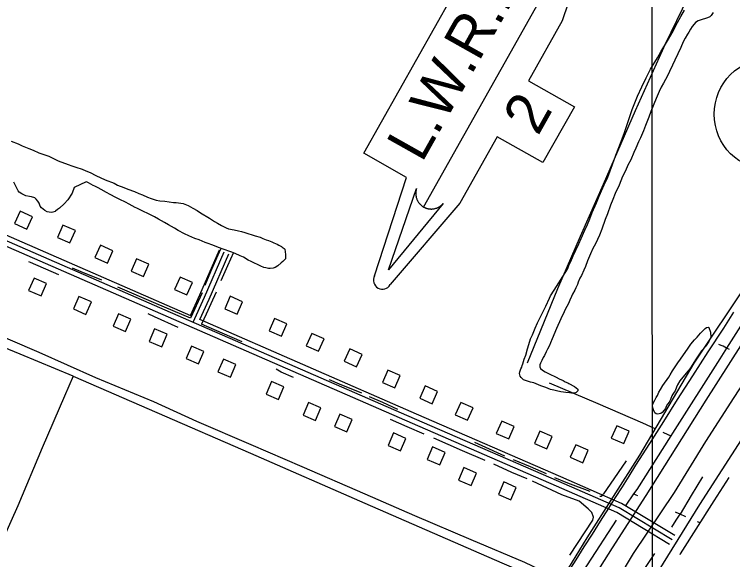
# Model space of a CAD drawing. Extents: x 3297735 to 3335592, y 670436 to 695807.
# Drawn here: x 3310478 to 3312597, y 691708 to 693317 of the extents above; entities that cross this region are included whole.
import ezdxf

# ---------------------------------------------------------------- set-up
doc = ezdxf.new("R2010")
doc.units = 0
for name, color, linetype in [('V-BLDG-OTLN', 7, 'Continuous'), ('V-DTCH-CNTR', 7, 'Continuous'), ('V-GRID-MAJR', 7, 'Continuous'), ('V-RAIL-TRAK', 7, 'Continuous'), ('V-ROAD-CNTR', 7, 'Continuous'), ('V-ROAD-IDEN', 7, 'Continuous'), ('V-SITE-VEGE', 7, 'Continuous'), ('V-TOPO-SHOR', 7, 'Continuous'), ('V-TOPO-WATR-IDEN', 7, 'Continuous')]:
    doc.layers.add(name, color=color, linetype=linetype)

msp = doc.modelspace()

# ---------------------------------------------------------------- linework, layer by layer
at = {"layer": 'V-BLDG-OTLN'}
for points in [[(3310478.7, 692699.8), (3310515.2, 692683.6), (3310531.4, 692720.2), (3310494.9, 692736.4)], [(3310605.3, 692658.8), (3310641.9, 692642.6), (3310658.1, 692679.2), (3310621.5, 692695.4)], [(3310716, 692599.5), (3310752.6, 692583.3), (3310768.8, 692619.9), (3310732.2, 692636.1)], [(3310822.4, 692559.7), (3310859, 692543.5), (3310875.2, 692580.1), (3310838.6, 692596.3)], [(3310950.8, 692505.7), (3310987.4, 692489.5), (3311003.6, 692526), (3310967, 692542.2)], [(3310572.9, 692522.9), (3310536.2, 692538.8), (3310520.3, 692502.1), (3310557.1, 692486.2)], [(3310705.3, 692468.6), (3310668.6, 692484.5), (3310652.8, 692447.8), (3310689.5, 692431.9)], [(3311098.7, 692448.6), (3311135.4, 692432.7), (3311151.3, 692469.4), (3311114.6, 692485.3)], [(3310821.9, 692418), (3310785.2, 692433.8), (3310769.4, 692397.1), (3310806.1, 692381.2)], [(3311229.5, 692383.7), (3311266, 692367.5), (3311282.2, 692404), (3311245.7, 692420.2)], [(3310928.8, 692373.1), (3310892.1, 692389), (3310876.2, 692352.3), (3310912.9, 692336.4)], [(3311339.3, 692339.2), (3311375.9, 692323), (3311392.1, 692359.6), (3311355.5, 692375.8)], [(3311037.5, 692322.4), (3311000.8, 692338.2), (3310984.9, 692301.5), (3311021.6, 692285.6)], [(3311451.5, 692293.5), (3311488, 692277.3), (3311504.2, 692313.8), (3311467.7, 692330)], [(3311131.5, 692283.6), (3311094.8, 692299.4), (3311078.9, 692262.7), (3311115.6, 692246.8)], [(3311563.8, 692231), (3311600.3, 692214.8), (3311616.5, 692251.4), (3311580, 692267.6)], [(3311273.4, 692217.6), (3311236.6, 692233.5), (3311220.8, 692196.8), (3311257.5, 692180.9)], [(3311674.2, 692184.2), (3311710.7, 692168), (3311726.9, 692204.6), (3311690.4, 692220.8)], [(3311382.3, 692155.8), (3311345.6, 692171.6), (3311329.8, 692134.9), (3311366.5, 692119.1)], [(3311778.7, 692135.3), (3311815.3, 692119.2), (3311831.5, 692155.7), (3311794.9, 692171.9)], [(3311474.9, 692121.7), (3311438.2, 692137.6), (3311422.3, 692100.9), (3311459.1, 692085)], [(3311899.9, 692080.7), (3311936.5, 692064.5), (3311952.7, 692101), (3311916.1, 692117.2)], [(3312239.2, 692066.6), (3312275.8, 692050.4), (3312292, 692087), (3312255.4, 692103.2)], [(3311633.4, 692065.9), (3311596.6, 692081.8), (3311580.8, 692045), (3311617.5, 692029.2)], [(3312012.6, 692050.9), (3312049.1, 692034.7), (3312065.3, 692071.3), (3312028.8, 692087.5)], [(3311748.9, 692024.7), (3311712.2, 692040.5), (3311696.4, 692003.8), (3311733.1, 691987.9)], [(3312118.2, 692010.4), (3312154.8, 691994.2), (3312171, 692030.8), (3312134.4, 692047)], [(3311841.4, 691963.7), (3311804.7, 691979.5), (3311788.9, 691942.8), (3311825.6, 691927)], [(3311958.6, 691921.3), (3311921.9, 691937.2), (3311906, 691900.4), (3311942.7, 691884.6)]]:
    msp.add_lwpolyline(points, close=True, dxfattribs=at)
at = {"layer": 'V-DTCH-CNTR'}
for points in [[(3312747.8, 694010.5), (3312706.8, 693904.1), (3312691, 693859.3), (3312664.3, 693798.2), (3312650.6, 693773.8), (3312638.3, 693754.1), (3312626, 693733.8), (3312613, 693711.4), (3312602.8, 693690.4), (3312573.9, 693631.7), (3312545.1, 693554.3), (3312481.3, 693402.3), (3312398.5, 693229.3), (3312309.4, 693032.6), (3312215.6, 692815.5), (3312147.7, 692661.4), (3312080.6, 692507.4), (3311991.5, 692287.5)], [(3310651.5, 692249.7), (3310495.5, 692314.6), (3310272.2, 692406.2), (3310049.6, 692502.6), (3309907.3, 692567.5), (3309884.3, 692579.9)], [(3310651.5, 692249.7), (3310626.4, 692190.3), (3310560.3, 692037.9), (3310488.6, 691866.6), (3310417.4, 691710.2), (3310375.3, 691610.6), (3310321.6, 691477.1), (3310262, 691344.5), (3310197.8, 691183.9), (3310147.1, 691059.4), (3310127.2, 691013), (3310087.6, 690919.2), (3310081, 690904.6)], [(3310651.5, 692249.7), (3310898.5, 692142.2), (3311175.3, 692022.3), (3311511.8, 691874.3), (3311893.8, 691708.5), (3311996.2, 691664.6)]]:
    msp.add_lwpolyline(points, dxfattribs=at)
at = {"layer": 'V-GRID-MAJR'}
msp.add_lwpolyline([(3312375.1, 675822.7), (3312373.9, 677215.6), (3312371.7, 679737.2), (3312369.1, 682705.7), (3312367.8, 684205.7), (3312365.9, 686440.1), (3312363.4, 689216.6), (3312360.3, 692823.2), (3312359.3, 694007.2)], dxfattribs=at)
at = {"layer": 'V-RAIL-TRAK'}
for points in [[(3312231.6, 691860.4), (3312252, 691891.7), (3312272.2, 691923.1), (3312292.2, 691954.7), (3312311.9, 691986.4), (3312353.1, 692051.1), (3312394.1, 692115.8), (3312434.8, 692180.7), (3312479.9, 692250.9), (3312525.2, 692321), (3312570.8, 692390.9), (3312600.3, 692438.3)], [(3312099, 691650.2), (3312110.7, 691669.3), (3312135.2, 691707.3), (3312159.6, 691745.4), (3312183.8, 691783.6), (3312207.8, 691821.9), (3312231.6, 691860.4)]]:
    msp.add_lwpolyline(points, dxfattribs=at)
at = {"layer": 'V-ROAD-CNTR'}
for points in [[(3313189.2, 693231.9), (3312861.3, 692717), (3312518.5, 692178.8), (3312341.6, 691897.3), (3312242.3, 691742.4), (3312038.3, 691420.5), (3311841.3, 691109), (3311668.6, 690842.8), (3311504, 690585), (3311408.2, 690444.7), (3311309.2, 690278.1), (3311173.2, 690061.5), (3311058.2, 689890.8)], [(3312419.1, 691766.1), (3312262.7, 691860.6), (3312084, 691938.6), (3311658.6, 692123.8), (3310993.2, 692414.2), (3310034.6, 692832.2), (3309899.5, 692893.8), (3309553.3, 693034.1)], [(3313225.9, 693012.8), (3312927.4, 692557.2), (3312688.4, 692164.2), (3312499.1, 691871), (3312353.9, 691636.1), (3312293.2, 691547), (3312159.4, 691339.8), (3312033.4, 691146.4), (3311880.5, 690903.5), (3311700.1, 690619.8), (3311629.8, 690502.5), (3311539.4, 690360.1), (3311438.5, 690202.4), (3311312.8, 690002.2), (3311226.4, 689864.9)], [(3312211.2, 691569.6), (3312305.1, 691726.5), (3312425.4, 691906), (3312517.7, 692057), (3312601.5, 692186.5), (3312684.8, 692313), (3312748.6, 692415.4), (3312814.9, 692521.5), (3312889.9, 692643.2), (3312978.4, 692789.2), (3313074.3, 692931.7), (3313120.6, 693003.5)], [(3310999.2, 692428), (3310999.2, 692428), (3310040.7, 692845.9), (3310005.9, 692861.8)], [(3310989.4, 689923.2), (3311166.1, 690197.8), (3311352.6, 690492.2), (3311553.7, 690809.1), (3311739.6, 691100.5), (3311901.8, 691353), (3312049.3, 691577.8), (3312168.1, 691772.4), (3312323.3, 692016.1), (3312483.8, 692287.8), (3312642.5, 692524.8), (3312756.2, 692696.5), (3312827.1, 692802.6), (3312864.6, 692857.4)], [(3312411.4, 691753.2), (3312255.8, 691847.3), (3312078, 691924.8), (3311652.6, 692110.1), (3310987.2, 692400.5), (3310028.5, 692818.5), (3309995.6, 692833.5)], [(3310998.2, 692428.4), (3311025.8, 692489.1), (3311083.3, 692622.2)], [(3311005.7, 692408.8), (3311039.5, 692483), (3311097.1, 692616.2)], [(3311025.7, 692416.4), (3311053.2, 692476.9), (3311110.9, 692610.3)], [(3312426.9, 691778.9), (3312269.6, 691874), (3312089.9, 691952.3), (3311664.6, 692137.6), (3311025.7, 692416.4)]]:
    msp.add_lwpolyline(points, dxfattribs=at)
at = {"layer": 'V-ROAD-IDEN'}
msp.add_circle((3312707.9, 693022.9), 165, dxfattribs=at)
at = {"layer": 'V-SITE-VEGE'}
for points in [[(3312070.7, 692503.6), (3312110, 692565.2), (3312110.9, 692567.2), (3312114.9, 692579.1), (3312119.4, 692588), (3312126.9, 692604.7), (3312143.8, 692639.8), (3312150.8, 692655.6), (3312161.3, 692680.3), (3312168.8, 692697), (3312176.2, 692714.3), (3312183.2, 692732.6), (3312195.2, 692760.7), (3312203.7, 692781), (3312218.1, 692814), (3312228.6, 692837.2), (3312243.1, 692874.3), (3312253, 692901.4), (3312268.5, 692941.9), (3312278, 692969.1), (3312291.5, 693010.5), (3312301, 693036.2), (3312316.4, 693076.2), (3312329.4, 693103.3), (3312341.8, 693130), (3312354.8, 693155.7), (3312375.7, 693189.2), (3312385.6, 693206.5), (3312408, 693244.5), (3312421.4, 693268.1), (3312429.4, 693284.9), (3312444.8, 693311.1), (3312455.3, 693329.3)], [(3312539.8, 693322.6), (3312534.3, 693313.7), (3312529.9, 693310.3), (3312522.9, 693306.8), (3312517, 693304.9), (3312507.6, 693302.4), (3312501.2, 693300.5), (3312495.7, 693298.5), (3312487.3, 693293.6), (3312483.3, 693288.7), (3312478.3, 693281.8), (3312473.4, 693273.9), (3312467.9, 693264.5), (3312463.9, 693258.6), (3312457, 693246.8), (3312451.5, 693235.9), (3312444.5, 693219.1), (3312427.1, 693182.1), (3312419.6, 693167.8), (3312411.1, 693149), (3312407.1, 693139.7), (3312399.2, 693124.9), (3312393.2, 693114.5), (3312386.7, 693102.6), (3312380.3, 693089.8), (3312371.3, 693069.1), (3312355.8, 693031.1)], [(3312355.8, 693031.1), (3312349.8, 693014.3), (3312340.4, 692989.1), (3312333.9, 692973.8), (3312325.9, 692953.1), (3312319.9, 692941.2), (3312311.9, 692922.5), (3312305.5, 692909.6), (3312296.5, 692887.9), (3312288.5, 692872.6), (3312281.1, 692855.3), (3312272.6, 692838.6), (3312262.1, 692813.4), (3312250.7, 692788.2), (3312244.2, 692771.4), (3312237.2, 692754.6), (3312228.2, 692729), (3312221.2, 692711.7), (3312211.2, 692683.5), (3312204.2, 692665.3), (3312192.8, 692640.1), (3312184.8, 692626.3), (3312177.8, 692611), (3312169.4, 692590.2), (3312163.4, 692573.5), (3312158.4, 692562.6), (3312151.4, 692546.8), (3312146.9, 692538.4), (3312142, 692526.6), (3312139.5, 692519.7), (3312134.5, 692509.8), (3312131.5, 692502.9), (3312125, 692491.5), (3312121.5, 692484.6), (3312116.6, 692474.3), (3312112.6, 692464.4), (3312103.1, 692446.1), (3312100.6, 692439.2), (3312090.6, 692418.5), (3312077.7, 692390.3), (3312065.2, 692359.7), (3312060.2, 692347.9), (3312056.7, 692340), (3312051.3, 692329.1), (3312046.8, 692321.2), (3312041.8, 692310.9), (3312038.3, 692304.5), (3312034.3, 692296.1), (3312029.9, 692287.7), (3312028.9, 692282.7), (3312028.8, 692276.8), (3312030.8, 692272.4), (3312036.7, 692266.9), (3312044.1, 692262.4), (3312056, 692256.5), (3312076.7, 692246.5), (3312085.1, 692241.5), (3312096.9, 692236.5), (3312103.3, 692233), (3312110.7, 692229.6), (3312113.7, 692228.1), (3312131, 692219.1), (3312140.8, 692211.2), (3312140.8, 692206.2), (3312135.9, 692201.3), (3312130.9, 692199.8), (3312122, 692199.4), (3312115.6, 692199.9), (3312104.7, 692201.4), (3312098.3, 692202.4), (3312089.9, 692203.4), (3312078, 692205.9), (3312070.1, 692207.9), (3312059.7, 692210), (3312053.3, 692213), (3312045.9, 692215.9), (3312031.1, 692221.4), (3312010.4, 692229.9), (3312001, 692231.9), (3311980.3, 692238.9), (3311973.8, 692245.4), (3311970.4, 692249.3), (3311968.9, 692257.7), (3311969, 692262.7), (3311972.5, 692271.1), (3311974.9, 692276), (3311976, 692281), (3311978.4, 692286.4), (3311982.4, 692299.7), (3311986.9, 692311.1), (3311992.4, 692330.3), (3311996, 692343.2), (3312001, 692360), (3312006.4, 692371.8), (3312014.4, 692391.1), (3312021.9, 692407.4), (3312036.3, 692436.5), (3312045.8, 692456.2), (3312056.8, 692479.9), (3312060.2, 692486.3), (3312070.7, 692503.6)], [(3310468.9, 692942.9), (3310489.2, 692935.4), (3310501.5, 692929.4), (3310521.3, 692921.9), (3310533.6, 692916.9), (3310550.4, 692908.9), (3310562.3, 692905), (3310580, 692898.5), (3310591.9, 692893), (3310607.7, 692885), (3310637.3, 692874.5), (3310648.1, 692870), (3310660, 692866), (3310677.8, 692860.5), (3310688.6, 692855.6), (3310701.5, 692850.6), (3310718.7, 692842.1), (3310745.9, 692829.2), (3310772.6, 692818.7), (3310782.4, 692813.7), (3310800.7, 692806.7), (3310813, 692801.7), (3310832.8, 692794.2), (3310845.1, 692788.3), (3310856.5, 692784.3), (3310870.8, 692777.8), (3310881.7, 692773.8), (3310897, 692769.3), (3310907.3, 692767.3), (3310922.2, 692765.7), (3310947.4, 692762.2), (3310955.8, 692761.7), (3310969.6, 692760.6), (3310976.5, 692759.1), (3310986.4, 692755.6), (3310991.3, 692753.1), (3311005.1, 692745.2), (3311017.5, 692738.2), (3311027.3, 692731.7), (3311053.5, 692716.3), (3311068.8, 692706.4), (3311077.7, 692701.4), (3311089.5, 692694.4), (3311094.9, 692691), (3311103.3, 692687.5), (3311109.7, 692684.5), (3311126.5, 692681), (3311139.4, 692678.5), (3311148.3, 692676.4), (3311158.2, 692673.4), (3311166.5, 692670.4), (3311179.9, 692666.4), (3311188.8, 692663.4), (3311203.6, 692659.4), (3311211, 692655.5), (3311221.4, 692651.5), (3311227.8, 692649.5), (3311237.6, 692646)], [(3311241.3, 692568.3), (3311232.9, 692566.9), (3311227.5, 692566.9), (3311220.1, 692568.9), (3311213.7, 692570.4), (3311205.3, 692573.9), (3311176.6, 692587.8), (3311168.2, 692592.3), (3311154.4, 692600.8), (3311144.6, 692604.8), (3311129.8, 692611.2), (3311119.4, 692615.2), (3311091.2, 692625.2), (3311075.4, 692631.7), (3311064.1, 692635.7), (3311047.3, 692642.2), (3311041.4, 692644.2), (3311023.1, 692651.7), (3311010.3, 692656.2), (3310992.5, 692664.1), (3310979.7, 692669.6), (3310961.4, 692679.6), (3310950.6, 692686), (3310932.8, 692696), (3310921, 692703), (3310903.7, 692713.4), (3310891.8, 692719.9), (3310872.1, 692729.8), (3310858.8, 692735.8), (3310839.5, 692745.3), (3310834.1, 692747.8), (3310817.3, 692757.2), (3310806, 692762.7), (3310789.7, 692771.2), (3310777.8, 692776.6), (3310761.1, 692786.1), (3310750.2, 692792.1), (3310733.9, 692800.5), (3310725.5, 692805.5), (3310715.2, 692810.5), (3310710.2, 692812.5), (3310703.8, 692816.4), (3310696.9, 692820.4), (3310693, 692821.9), (3310690, 692823.4), (3310654.8, 692806.7), (3310648.9, 692789.9), (3310635.9, 692769.7), (3310625.5, 692757.9), (3310611.6, 692745.1), (3310605.2, 692741.2), (3310599.7, 692736.7), (3310598.2, 692735.2), (3310591.8, 692733.3), (3310586.4, 692732.8), (3310575, 692734.8), (3310567.6, 692738.3), (3310558.2, 692746.3), (3310554.8, 692751.7), (3310550.9, 692760.6), (3310547.9, 692765.6), (3310543, 692772), (3310538.1, 692775.5), (3310529.2, 692779), (3310522.8, 692780), (3310511.9, 692782), (3310500.5, 692787.5), (3310492.6, 692792.5), (3310489.2, 692796.9), (3310476.9, 692821.7)], [(3311237.6, 692646), (3311244.1, 692643.5), (3311253.5, 692639.5), (3311258.4, 692636.5), (3311266.3, 692632.5), (3311268.2, 692630.5), (3311273.7, 692626.1), (3311276.1, 692624.6), (3311278.1, 692608.7), (3311278.5, 692600.8), (3311278, 692595.4), (3311270.1, 692587.5), (3311265.6, 692583.6), (3311255.7, 692575.2), (3311247.8, 692570.3), (3311241.3, 692568.3)]]:
    msp.add_lwpolyline(points, dxfattribs=at)
msp.add_lwpolyline([(3312441.5, 692235.8), (3312435, 692223.5), (3312431.5, 692216.6), (3312427.6, 692206.7), (3312424.6, 692202.2), (3312420.6, 692196.8), (3312418.1, 692191.9), (3312414.1, 692181), (3312409.6, 692173.1), (3312404.7, 692166.7), (3312400.7, 692159.8), (3312398.7, 692153.9), (3312395.7, 692148.9), (3312389.3, 692142.5), (3312385.3, 692139.6), (3312380.8, 692138.1), (3312376.9, 692137.6), (3312371.4, 692138.2), (3312367.5, 692141.1), (3312363.6, 692150.1), (3312361.6, 692156.5), (3312360.7, 692164.4), (3312363.2, 692169.8), (3312367.6, 692178.7), (3312371.6, 692186.1), (3312375.1, 692192), (3312379.6, 692202.4), (3312384.1, 692210.3), (3312391, 692221.6), (3312396, 692228.5), (3312404.4, 692239.4), (3312409.4, 692246.8), (3312413.4, 692253.7), (3312419.9, 692265.5), (3312435.3, 692289.2), (3312443.2, 692300.1), (3312466.1, 692332.6), (3312474, 692343.5), (3312484.5, 692356.8), (3312492.9, 692365.1), (3312502.8, 692376.5), (3312508.3, 692382.4), (3312516.2, 692390.3), (3312519.7, 692393.2), (3312524.6, 692394.2), (3312527.1, 692393.2), (3312531.5, 692379.8), (3312532.9, 692365), (3312526.9, 692351.7), (3312521.5, 692343.3), (3312516, 692335.9), (3312505.6, 692324.1), (3312499.1, 692315.7), (3312489.2, 692300.9), (3312482.7, 692289.5), (3312473.3, 692274.2), (3312467.3, 692265.9), (3312465.3, 692263.9)], close=True, dxfattribs=at)
at = {"layer": 'V-TOPO-SHOR'}
for p, q in [((3311031.9, 692495.2), (3310998.1, 692420.8)), ((3312588.4, 692328.3), (3312579.6, 692332)), ((3312501.1, 691816.6), (3312493.7, 691819.9))]:
    msp.add_line(p, q, dxfattribs=at)
for points in [[(3313202.8, 693313.8), (3313129.6, 693200), (3313027.2, 693042.1), (3312989.6, 692982.6), (3312915.8, 692866), (3312838.3, 692741.4), (3312814.6, 692703.2), (3312687.1, 692502.3), (3312579.6, 692332), (3312559.7, 692300.6), (3312420, 692081.5), (3312414.8, 692073.4), (3312314.2, 691915), (3312304.9, 691901.8), (3312281.7, 691868.7)], [(3311041.3, 692518.2), (3311061.1, 692565.4), (3311087.3, 692625.3)], [(3311124.6, 692614.4), (3311107.1, 692575.5), (3311087.6, 692530.6)], [(3310609.6, 692549.1), (3310526, 692584.8), (3310521.3, 692586.9)], [(3310736.1, 692532.4), (3310675, 692557.8), (3310649.8, 692568.1)], [(3310998.1, 692420.8), (3310895.1, 692463.8), (3310783.7, 692511.8)], [(3311073.5, 692497.6), (3311057.8, 692463.2), (3311044.1, 692432.5), (3311030.3, 692403.4)], [(3310961.5, 692392.8), (3310891.6, 692425), (3310872.5, 692433.9)], [(3311150.5, 692350.6), (3311069, 692386.2), (3311030.3, 692403.4)], [(3312119.9, 691620.3), (3312055.8, 691665.1), (3311984.6, 691699.6), (3311825.8, 691766.6), (3311659.2, 691837.5), (3311513, 691901.5), (3311327.2, 691981.7), (3311176.5, 692047.3), (3311016.2, 692115.8), (3310889.7, 692173.5), (3310718.7, 692245.1), (3310551, 692318.9), (3310388.5, 692388.9)], [(3312579.6, 692332), (3312569.1, 692337.9), (3312563.3, 692340.3), (3312556.1, 692342.8)], [(3311301.9, 692245.2), (3311265.2, 692261.7), (3311250.3, 692269.9)], [(3311503.2, 692198.9), (3311437.3, 692225.7), (3311408, 692238.7)], [(3312055.9, 692230.1), (3312199.1, 692169), (3312331.2, 692111.7), (3312367.5, 692094.7)], [(3311609.8, 692150.9), (3311564.9, 692171.7), (3311525.6, 692188.7)], [(3311687.1, 692078.5), (3311637.2, 692100.4), (3311587.9, 692121.7)], [(3312390.9, 692083.8), (3312392.8, 692082.9), (3312414.8, 692073.4)], [(3311867.2, 692001), (3311799.9, 692029.1), (3311715.7, 692066.2)], [(3311925.1, 692013), (3311868.7, 692039.1), (3311836.7, 692053.5)], [(3312048, 691961.6), (3312001.2, 691981.5), (3311950.9, 692002.7)], [(3312282.9, 691999.5), (3312236.4, 691931), (3312216.6, 691902.4), (3312211.8, 691897.7), (3312209.1, 691894.3), (3312205, 691894.3)], [(3311990.8, 691946.8), (3311946, 691965.3), (3311892.3, 691990)], [(3312176.5, 691908.7), (3312111.2, 691933.4), (3312072.5, 691949.2)], [(3312585.8, 691950.8), (3312542.2, 691881.2), (3312442.9, 691725.1), (3312441.2, 691722.6)], [(3312507.9, 691952.7), (3312474.6, 691897.8), (3312442.1, 691842.2)], [(3312116.6, 691721.1), (3312185, 691824.3), (3312187.1, 691833.8), (3312181.7, 691846.8), (3312171.5, 691857.7), (3312144.4, 691880.2), (3312093.4, 691899.5), (3312006.5, 691939.9)], [(3312317.3, 691896.3), (3312312.6, 691898.3), (3312304.9, 691901.8)], [(3312459.3, 691834.7), (3312442.1, 691842.2), (3312431, 691847), (3312428.2, 691848.2)], [(3312253.3, 691824.9), (3312168.5, 691692.6), (3312119.9, 691620.3)], [(3312417.8, 691803.9), (3312430.5, 691824.3), (3312442.1, 691842.2)], [(3312366.3, 691725.9), (3312275.1, 691589.4), (3312183.2, 691437), (3312092.4, 691282.3), (3312080.5, 691289.6)]]:
    msp.add_lwpolyline(points, dxfattribs=at)
at = {"layer": 'V-TOPO-WATR-IDEN'}
msp.add_line((3311685.7, 692748.8), (3312054, 693403.5), dxfattribs=at)
for points in [[(3311541, 692545.6), (3311634.9, 692836.3), (3311508.8, 692907.3), (3311821.8, 693463.8), (3311947.9, 693392.8), (3312152.5, 693632.6)], [(3312198.7, 693606.6), (3312094.8, 693298.1), (3311995, 693120.8), (3312130.4, 693044.7), (3312037.7, 692879.9), (3311902.3, 692956), (3311792.1, 692760.1), (3311587.2, 692519.6)]]:
    msp.add_lwpolyline(points, dxfattribs=at)
msp.add_lwpolyline([(3311743.3, 692759.4), (3311581.6, 692563.6), (3311664.9, 692803.5), (3311663.6, 692799.1), (3311662.8, 692794.8), (3311662.6, 692793), (3311662.5, 692791.5), (3311662.4, 692789.6), (3311662.4, 692787.8), (3311662.5, 692786.2), (3311662.6, 692784), (3311662.9, 692781.7), (3311663.1, 692780.4), (3311663.5, 692778.8), (3311664, 692776.6), (3311664.5, 692775), (3311665.1, 692773.2), (3311665.5, 692772.1), (3311666, 692770.8), (3311666.7, 692769.3), (3311667.3, 692768), (3311668, 692766.6), (3311668.6, 692765.6), (3311669.6, 692764), (3311670.6, 692762.5), (3311671.4, 692761.4), (3311672.4, 692760.1), (3311673.3, 692759), (3311674.1, 692758), (3311674.8, 692757.3), (3311675.9, 692756.2), (3311677, 692755.2), (3311678.1, 692754.2), (3311679.2, 692753.2), (3311680.3, 692752.4), (3311681.5, 692751.4), (3311682.5, 692750.7), (3311684, 692749.8), (3311685.7, 692748.8), (3311686.3, 692748.5), (3311687.1, 692748), (3311688.1, 692747.5), (3311689, 692747.1), (3311690, 692746.7), (3311690.9, 692746.3), (3311692, 692745.8), (3311692.8, 692745.5), (3311693.9, 692745.2), (3311695, 692744.8), (3311695.8, 692744.6), (3311697.7, 692744.1), (3311698.8, 692743.9), (3311699.5, 692743.7), (3311700.7, 692743.5), (3311701.8, 692743.3), (3311702.9, 692743.2), (3311704.3, 692743.1), (3311705.5, 692743), (3311706.5, 692742.9), (3311707.4, 692742.9), (3311708.5, 692742.9), (3311709.5, 692742.9), (3311710.7, 692743), (3311711.9, 692743.1), (3311713.1, 692743.2), (3311714.7, 692743.4), (3311715.8, 692743.5), (3311717, 692743.8), (3311718.2, 692744), (3311719.1, 692744.2), (3311720.1, 692744.5), (3311721.6, 692744.9), (3311721.7, 692744.9), (3311722.6, 692745.2), (3311723.2, 692745.5), (3311724.2, 692745.8), (3311725.4, 692746.3), (3311726.4, 692746.7), (3311727.2, 692747.1), (3311728.3, 692747.6), (3311729.3, 692748.1), (3311730, 692748.5), (3311730.9, 692749), (3311732.2, 692749.7), (3311732.9, 692750.2), (3311733.5, 692750.6), (3311734, 692750.9), (3311734.6, 692751.3), (3311735.4, 692751.9), (3311736.2, 692752.5), (3311736.9, 692753.1), (3311737.7, 692753.7), (3311738.6, 692754.5), (3311739.2, 692755), (3311740, 692755.9), (3311741, 692756.8), (3311741.7, 692757.6), (3311742.3, 692758.2), (3311742.7, 692758.7), (3311743.1, 692759.1)], close=True, dxfattribs=at)
msp.add_arc((3311564.1, 692532.6), 26.5, 150.6427, 330.6427, dxfattribs=at)

# ---------------------------------------------------------------- texts
for s, rotation, p in [('L.W.R.P.', 60.6426, (3311680.4, 692877)), ('2', 60.6427, (3312022.7, 692956.2))]:
    msp.add_text(s, height=124.5, rotation=rotation, dxfattribs=at).set_placement(p)

doc.saveas('drawing.dxf')
